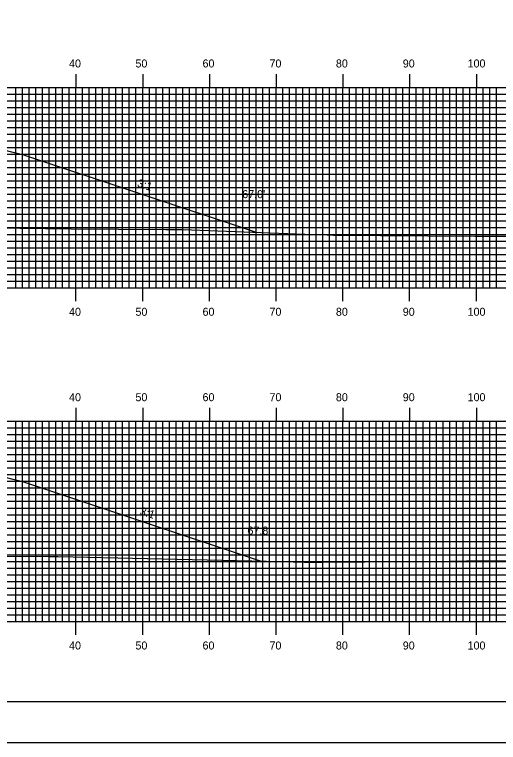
# Model space of a CAD drawing. Extents: x 1806651 to 1806995, y 442591 to 442811.
# Drawn here: x 1806848.1 to 1806920.6, y 442590.5 to 442699.6 of the extents above; entities that cross this region are included whole.
import ezdxf

# ---------------------------------------------------------------- set-up
doc = ezdxf.new("R2010")
doc.units = 0
for name, color, linetype in [('ANNOTATION', 7, 'Continuous'), ('BORDER', 7, 'Continuous'), ('D_Roadway_Centerline', 7, 'Continuous'), ('D_Roadway_SlopeLines', 7, 'Continuous'), ('D_Text_Standard', 7, 'Continuous'), ('H_V ANNOTATION', 7, 'Continuous'), ('MAJOR', 7, 'Continuous'), ('MINOR', 7, 'Continuous'), ('PLOT BOUNDARY', 7, 'Continuous'), ('S_Roadway_Centerline', 7, 'Continuous')]:
    doc.layers.add(name, color=color, linetype=linetype)

msp = doc.modelspace()

# ---------------------------------------------------------------- linework, layer by layer
at = {"layer": 'BORDER'}
msp.add_lwpolyline([(1806667.65, 442596.67), (1806987.65, 442596.67), (1806987.65, 442806.67), (1806667.65, 442806.67)], close=True, dxfattribs=at)
at = {"layer": 'D_Roadway_Centerline'}
for points in [[(1806757.98, 442669.56), (1806785.25, 442678.65), (1806787.07, 442679.1), (1806797.25, 442681.65), (1806805.25, 442681.97), (1806817.25, 442682.21), (1806829.25, 442681.97), (1806837.25, 442681.65), (1806847.42, 442679.1), (1806849.25, 442678.65), (1806884.23, 442666.99)], [(1806759.56, 442621.08), (1806785.25, 442629.65), (1806787.07, 442630.1), (1806797.25, 442632.65), (1806805.25, 442632.97), (1806817.25, 442633.21), (1806829.25, 442632.97), (1806837.25, 442632.65), (1806847.42, 442630.1), (1806849.25, 442629.65), (1806885.01, 442617.73)]]:
    msp.add_lwpolyline(points, dxfattribs=at)
at = {"layer": 'D_Roadway_SlopeLines'}
for points in [[(1806837.25, 442681.65), (1806849.25, 442678.65), (1806884.23, 442666.99)], [(1806837.25, 442632.65), (1806849.25, 442629.65), (1806885.01, 442617.73)]]:
    msp.add_lwpolyline(points, dxfattribs=at)
at = {"layer": 'MAJOR'}
for p, q in [((1806857.25, 442690.67), (1806857.25, 442688.67)), ((1806867.25, 442690.67), (1806867.25, 442688.67)), ((1806877.25, 442690.67), (1806877.25, 442688.67)), ((1806887.25, 442690.67), (1806887.25, 442688.67)), ((1806897.25, 442690.67), (1806897.25, 442688.67)), ((1806907.25, 442690.67), (1806907.25, 442688.67)), ((1806917.25, 442690.67), (1806917.25, 442688.67)), ((1806677.25, 442688.67), (1806957.25, 442688.67)), ((1806677.25, 442688.67), (1806957.25, 442688.67)), ((1806857.25, 442658.67), (1806857.25, 442688.67)), ((1806867.25, 442658.67), (1806867.25, 442688.67)), ((1806877.25, 442658.67), (1806877.25, 442688.67)), ((1806887.25, 442658.67), (1806887.25, 442688.67)), ((1806897.25, 442658.67), (1806897.25, 442688.67)), ((1806907.25, 442658.67), (1806907.25, 442688.67)), ((1806917.25, 442658.67), (1806917.25, 442688.67)), ((1806677.25, 442683.67), (1806957.25, 442683.67)), ((1806677.25, 442678.67), (1806957.25, 442678.67)), ((1806677.25, 442673.67), (1806957.25, 442673.67)), ((1806677.25, 442668.67), (1806957.25, 442668.67)), ((1806677.25, 442663.67), (1806957.25, 442663.67)), ((1806677.25, 442658.67), (1806957.25, 442658.67)), ((1806677.25, 442658.67), (1806957.25, 442658.67)), ((1806857.25, 442656.66), (1806857.25, 442658.67)), ((1806867.25, 442656.66), (1806867.25, 442658.67)), ((1806877.25, 442656.66), (1806877.25, 442658.67)), ((1806887.25, 442656.66), (1806887.25, 442658.67)), ((1806897.25, 442656.66), (1806897.25, 442658.67)), ((1806907.25, 442656.66), (1806907.25, 442658.67)), ((1806917.25, 442656.66), (1806917.25, 442658.67)), ((1806857.25, 442640.67), (1806857.25, 442638.67)), ((1806867.25, 442640.67), (1806867.25, 442638.67)), ((1806877.25, 442640.67), (1806877.25, 442638.67)), ((1806887.25, 442640.67), (1806887.25, 442638.67)), ((1806897.25, 442640.67), (1806897.25, 442638.67)), ((1806907.25, 442640.67), (1806907.25, 442638.67)), ((1806917.25, 442640.67), (1806917.25, 442638.67)), ((1806677.25, 442638.67), (1806957.25, 442638.67)), ((1806677.25, 442638.67), (1806957.25, 442638.67)), ((1806857.25, 442608.67), (1806857.25, 442638.67)), ((1806867.25, 442608.67), (1806867.25, 442638.67)), ((1806877.25, 442608.67), (1806877.25, 442638.67)), ((1806887.25, 442608.67), (1806887.25, 442638.67)), ((1806897.25, 442608.67), (1806897.25, 442638.67)), ((1806907.25, 442608.67), (1806907.25, 442638.67)), ((1806917.25, 442608.67), (1806917.25, 442638.67)), ((1806677.25, 442633.67), (1806957.25, 442633.67)), ((1806677.25, 442628.67), (1806957.25, 442628.67)), ((1806677.25, 442623.67), (1806957.25, 442623.67)), ((1806677.25, 442618.67), (1806957.25, 442618.67)), ((1806677.25, 442613.67), (1806957.25, 442613.67)), ((1806677.25, 442608.67), (1806957.25, 442608.67)), ((1806677.25, 442608.67), (1806957.25, 442608.67)), ((1806857.25, 442606.66), (1806857.25, 442608.67)), ((1806867.25, 442606.66), (1806867.25, 442608.67)), ((1806877.25, 442606.66), (1806877.25, 442608.67)), ((1806887.25, 442606.66), (1806887.25, 442608.67)), ((1806897.25, 442606.66), (1806897.25, 442608.67)), ((1806907.25, 442606.66), (1806907.25, 442608.67)), ((1806917.25, 442606.66), (1806917.25, 442608.67))]:
    msp.add_line(p, q, dxfattribs=at)
at = {"layer": 'MINOR'}
for p, q in [((1806848.25, 442658.67), (1806848.25, 442688.67)), ((1806849.25, 442658.67), (1806849.25, 442688.67)), ((1806850.25, 442658.67), (1806850.25, 442688.67)), ((1806851.25, 442658.67), (1806851.25, 442688.67)), ((1806852.25, 442658.67), (1806852.25, 442688.67)), ((1806853.25, 442658.67), (1806853.25, 442688.67)), ((1806854.25, 442658.67), (1806854.25, 442688.67)), ((1806855.25, 442658.67), (1806855.25, 442688.67)), ((1806856.25, 442658.67), (1806856.25, 442688.67)), ((1806858.25, 442658.67), (1806858.25, 442688.67)), ((1806859.25, 442658.67), (1806859.25, 442688.67)), ((1806860.25, 442658.67), (1806860.25, 442688.67)), ((1806861.25, 442658.67), (1806861.25, 442688.67)), ((1806862.25, 442658.67), (1806862.25, 442688.67)), ((1806863.25, 442658.67), (1806863.25, 442688.67)), ((1806864.25, 442658.67), (1806864.25, 442688.67)), ((1806865.25, 442658.67), (1806865.25, 442688.67)), ((1806866.25, 442658.67), (1806866.25, 442688.67)), ((1806868.25, 442658.67), (1806868.25, 442688.67)), ((1806869.25, 442658.67), (1806869.25, 442688.67)), ((1806870.25, 442658.67), (1806870.25, 442688.67)), ((1806871.25, 442658.67), (1806871.25, 442688.67)), ((1806872.25, 442658.67), (1806872.25, 442688.67)), ((1806873.25, 442658.67), (1806873.25, 442688.67)), ((1806874.25, 442658.67), (1806874.25, 442688.67)), ((1806875.25, 442658.67), (1806875.25, 442688.67)), ((1806876.25, 442658.67), (1806876.25, 442688.67)), ((1806878.25, 442658.67), (1806878.25, 442688.67)), ((1806879.25, 442658.67), (1806879.25, 442688.67)), ((1806880.25, 442658.67), (1806880.25, 442688.67)), ((1806881.25, 442658.67), (1806881.25, 442688.67)), ((1806882.25, 442658.67), (1806882.25, 442688.67)), ((1806883.25, 442658.67), (1806883.25, 442688.67)), ((1806884.25, 442658.67), (1806884.25, 442688.67)), ((1806885.25, 442658.67), (1806885.25, 442688.67)), ((1806886.25, 442658.67), (1806886.25, 442688.67)), ((1806888.25, 442658.67), (1806888.25, 442688.67)), ((1806889.25, 442658.67), (1806889.25, 442688.67)), ((1806890.25, 442658.67), (1806890.25, 442688.67)), ((1806891.25, 442658.67), (1806891.25, 442688.67)), ((1806892.25, 442658.67), (1806892.25, 442688.67)), ((1806893.25, 442658.67), (1806893.25, 442688.67)), ((1806894.25, 442658.67), (1806894.25, 442688.67)), ((1806895.25, 442658.67), (1806895.25, 442688.67)), ((1806896.25, 442658.67), (1806896.25, 442688.67)), ((1806898.25, 442658.67), (1806898.25, 442688.67)), ((1806899.25, 442658.67), (1806899.25, 442688.67)), ((1806900.25, 442658.67), (1806900.25, 442688.67)), ((1806901.25, 442658.67), (1806901.25, 442688.67)), ((1806902.25, 442658.67), (1806902.25, 442688.67)), ((1806903.25, 442658.67), (1806903.25, 442688.67)), ((1806904.25, 442658.67), (1806904.25, 442688.67)), ((1806905.25, 442658.67), (1806905.25, 442688.67)), ((1806906.25, 442658.67), (1806906.25, 442688.67)), ((1806908.25, 442658.67), (1806908.25, 442688.67)), ((1806909.25, 442658.67), (1806909.25, 442688.67)), ((1806910.25, 442658.67), (1806910.25, 442688.67)), ((1806911.25, 442658.67), (1806911.25, 442688.67)), ((1806912.25, 442658.67), (1806912.25, 442688.67)), ((1806913.25, 442658.67), (1806913.25, 442688.67)), ((1806914.25, 442658.67), (1806914.25, 442688.67)), ((1806915.25, 442658.67), (1806915.25, 442688.67)), ((1806916.25, 442658.67), (1806916.25, 442688.67)), ((1806918.25, 442658.67), (1806918.25, 442688.67)), ((1806919.25, 442658.67), (1806919.25, 442688.67)), ((1806920.25, 442658.67), (1806920.25, 442688.67)), ((1806677.25, 442687.67), (1806957.25, 442687.67)), ((1806677.25, 442686.67), (1806957.25, 442686.67)), ((1806677.25, 442685.67), (1806957.25, 442685.67)), ((1806677.25, 442684.67), (1806957.25, 442684.67)), ((1806677.25, 442682.67), (1806957.25, 442682.67)), ((1806677.25, 442681.67), (1806957.25, 442681.67)), ((1806677.25, 442680.67), (1806957.25, 442680.67)), ((1806677.25, 442679.67), (1806957.25, 442679.67)), ((1806677.25, 442677.67), (1806957.25, 442677.67)), ((1806677.25, 442676.67), (1806957.25, 442676.67)), ((1806677.25, 442675.67), (1806957.25, 442675.67)), ((1806677.25, 442674.67), (1806957.25, 442674.67)), ((1806677.25, 442672.67), (1806957.25, 442672.67)), ((1806677.25, 442671.67), (1806957.25, 442671.67)), ((1806677.25, 442670.67), (1806957.25, 442670.67)), ((1806677.25, 442669.67), (1806957.25, 442669.67)), ((1806677.25, 442667.67), (1806957.25, 442667.67)), ((1806677.25, 442666.67), (1806957.25, 442666.67)), ((1806677.25, 442665.67), (1806957.25, 442665.67)), ((1806677.25, 442664.67), (1806957.25, 442664.67)), ((1806677.25, 442662.67), (1806957.25, 442662.67)), ((1806677.25, 442661.67), (1806957.25, 442661.67)), ((1806677.25, 442660.67), (1806957.25, 442660.67)), ((1806677.25, 442659.67), (1806957.25, 442659.67)), ((1806848.25, 442608.67), (1806848.25, 442638.67)), ((1806849.25, 442608.67), (1806849.25, 442638.67)), ((1806850.25, 442608.67), (1806850.25, 442638.67)), ((1806851.25, 442608.67), (1806851.25, 442638.67)), ((1806852.25, 442608.67), (1806852.25, 442638.67)), ((1806853.25, 442608.67), (1806853.25, 442638.67)), ((1806854.25, 442608.67), (1806854.25, 442638.67)), ((1806855.25, 442608.67), (1806855.25, 442638.67)), ((1806856.25, 442608.67), (1806856.25, 442638.67)), ((1806858.25, 442608.67), (1806858.25, 442638.67)), ((1806859.25, 442608.67), (1806859.25, 442638.67)), ((1806860.25, 442608.67), (1806860.25, 442638.67)), ((1806861.25, 442608.67), (1806861.25, 442638.67)), ((1806862.25, 442608.67), (1806862.25, 442638.67)), ((1806863.25, 442608.67), (1806863.25, 442638.67)), ((1806864.25, 442608.67), (1806864.25, 442638.67)), ((1806865.25, 442608.67), (1806865.25, 442638.67)), ((1806866.25, 442608.67), (1806866.25, 442638.67)), ((1806868.25, 442608.67), (1806868.25, 442638.67)), ((1806869.25, 442608.67), (1806869.25, 442638.67)), ((1806870.25, 442608.67), (1806870.25, 442638.67)), ((1806871.25, 442608.67), (1806871.25, 442638.67)), ((1806872.25, 442608.67), (1806872.25, 442638.67)), ((1806873.25, 442608.67), (1806873.25, 442638.67)), ((1806874.25, 442608.67), (1806874.25, 442638.67)), ((1806875.25, 442608.67), (1806875.25, 442638.67)), ((1806876.25, 442608.67), (1806876.25, 442638.67)), ((1806878.25, 442608.67), (1806878.25, 442638.67)), ((1806879.25, 442608.67), (1806879.25, 442638.67)), ((1806880.25, 442608.67), (1806880.25, 442638.67)), ((1806881.25, 442608.67), (1806881.25, 442638.67)), ((1806882.25, 442608.67), (1806882.25, 442638.67)), ((1806883.25, 442608.67), (1806883.25, 442638.67)), ((1806884.25, 442608.67), (1806884.25, 442638.67)), ((1806885.25, 442608.67), (1806885.25, 442638.67)), ((1806886.25, 442608.67), (1806886.25, 442638.67)), ((1806888.25, 442608.67), (1806888.25, 442638.67)), ((1806889.25, 442608.67), (1806889.25, 442638.67)), ((1806890.25, 442608.67), (1806890.25, 442638.67)), ((1806891.25, 442608.67), (1806891.25, 442638.67)), ((1806892.25, 442608.67), (1806892.25, 442638.67)), ((1806893.25, 442608.67), (1806893.25, 442638.67)), ((1806894.25, 442608.67), (1806894.25, 442638.67)), ((1806895.25, 442608.67), (1806895.25, 442638.67)), ((1806896.25, 442608.67), (1806896.25, 442638.67)), ((1806898.25, 442608.67), (1806898.25, 442638.67)), ((1806899.25, 442608.67), (1806899.25, 442638.67)), ((1806900.25, 442608.67), (1806900.25, 442638.67)), ((1806901.25, 442608.67), (1806901.25, 442638.67)), ((1806902.25, 442608.67), (1806902.25, 442638.67)), ((1806903.25, 442608.67), (1806903.25, 442638.67)), ((1806904.25, 442608.67), (1806904.25, 442638.67)), ((1806905.25, 442608.67), (1806905.25, 442638.67)), ((1806906.25, 442608.67), (1806906.25, 442638.67)), ((1806908.25, 442608.67), (1806908.25, 442638.67)), ((1806909.25, 442608.67), (1806909.25, 442638.67)), ((1806910.25, 442608.67), (1806910.25, 442638.67)), ((1806911.25, 442608.67), (1806911.25, 442638.67)), ((1806912.25, 442608.67), (1806912.25, 442638.67)), ((1806913.25, 442608.67), (1806913.25, 442638.67)), ((1806914.25, 442608.67), (1806914.25, 442638.67)), ((1806915.25, 442608.67), (1806915.25, 442638.67)), ((1806916.25, 442608.67), (1806916.25, 442638.67)), ((1806918.25, 442608.67), (1806918.25, 442638.67)), ((1806919.25, 442608.67), (1806919.25, 442638.67)), ((1806920.25, 442608.67), (1806920.25, 442638.67)), ((1806677.25, 442637.67), (1806957.25, 442637.67)), ((1806677.25, 442636.67), (1806957.25, 442636.67)), ((1806677.25, 442635.67), (1806957.25, 442635.67)), ((1806677.25, 442634.67), (1806957.25, 442634.67)), ((1806677.25, 442632.67), (1806957.25, 442632.67)), ((1806677.25, 442631.67), (1806957.25, 442631.67)), ((1806677.25, 442630.67), (1806957.25, 442630.67)), ((1806677.25, 442629.67), (1806957.25, 442629.67)), ((1806677.25, 442627.67), (1806957.25, 442627.67)), ((1806677.25, 442626.67), (1806957.25, 442626.67)), ((1806677.25, 442625.67), (1806957.25, 442625.67)), ((1806677.25, 442624.67), (1806957.25, 442624.67)), ((1806677.25, 442622.67), (1806957.25, 442622.67)), ((1806677.25, 442621.67), (1806957.25, 442621.67)), ((1806677.25, 442620.67), (1806957.25, 442620.67)), ((1806677.25, 442619.67), (1806957.25, 442619.67)), ((1806677.25, 442617.67), (1806957.25, 442617.67)), ((1806677.25, 442616.67), (1806957.25, 442616.67)), ((1806677.25, 442615.67), (1806957.25, 442615.67)), ((1806677.25, 442614.67), (1806957.25, 442614.67)), ((1806677.25, 442612.67), (1806957.25, 442612.67)), ((1806677.25, 442611.67), (1806957.25, 442611.67)), ((1806677.25, 442610.67), (1806957.25, 442610.67)), ((1806677.25, 442609.67), (1806957.25, 442609.67))]:
    msp.add_line(p, q, dxfattribs=at)
at = {"layer": 'PLOT BOUNDARY'}
msp.add_lwpolyline([(1806651.46, 442590.55), (1806991.46, 442590.55), (1806991.46, 442810.55), (1806651.46, 442810.55)], close=True, dxfattribs=at)
at = {"layer": 'S_Roadway_Centerline'}
for points in [[(1806821.89, 442667.95), (1806856.56, 442667.51), (1806870.7, 442667.4), (1806873.25, 442667.39), (1806891.61, 442666.72), (1806894.85, 442666.6), (1806895.82, 442666.57), (1806917, 442666.38), (1806919.2, 442666.38), (1806921.92, 442666.4), (1806944.01, 442666.14), (1806950.5, 442665.91), (1806955.14, 442665.87), (1806957.25, 442665.89)], [(1806835.26, 442618.46), (1806853.24, 442618.41), (1806854.41, 442618.41), (1806854.59, 442618.41), (1806888.04, 442617.66), (1806891.49, 442617.57), (1806894.18, 442617.58), (1806913.19, 442617.71), (1806915.76, 442617.74), (1806926.18, 442617.8), (1806930.78, 442617.41), (1806957.25, 442617.28)]]:
    msp.add_lwpolyline(points, dxfattribs=at)

# ---------------------------------------------------------------- texts
at = {"layer": 'ANNOTATION'}
for p in [(1806866.34, 442673.86), (1806866.73, 442624.73)]:
    msp.add_text('3:1', height=1.2, rotation=341.5652, dxfattribs=at).set_placement(p)
at = {"layer": 'D_Text_Standard'}
for s, p in [("67.0'", (1806882.17, 442672.09)), ("67.8'", (1806882.95, 442621.69))]:
    msp.add_text(s, height=1.2, dxfattribs=at).set_placement(p)
at = {"layer": 'H_V ANNOTATION'}
for s, p in [('40', (1806856.22, 442691.67)), ('50', (1806866.17, 442691.67)), ('60', (1806876.22, 442691.67)), ('70', (1806886.25, 442691.67)), ('80', (1806896.2, 442691.67)), ('90', (1806906.22, 442691.67)), ('100', (1806915.93, 442691.67)), ('40', (1806856.22, 442654.47)), ('50', (1806866.17, 442654.47)), ('60', (1806876.22, 442654.47)), ('70', (1806886.25, 442654.47)), ('80', (1806896.2, 442654.47)), ('90', (1806906.22, 442654.47)), ('100', (1806915.93, 442654.47)), ('40', (1806856.22, 442641.67)), ('50', (1806866.17, 442641.67)), ('60', (1806876.22, 442641.67)), ('70', (1806886.25, 442641.67)), ('80', (1806896.2, 442641.67)), ('90', (1806906.22, 442641.67)), ('100', (1806915.93, 442641.67)), ('40', (1806856.22, 442604.47)), ('50', (1806866.17, 442604.47)), ('60', (1806876.22, 442604.47)), ('70', (1806886.25, 442604.47)), ('80', (1806896.2, 442604.47)), ('90', (1806906.22, 442604.47)), ('100', (1806915.93, 442604.47))]:
    msp.add_text(s, height=1.2, dxfattribs=at).set_placement(p)

doc.saveas('drawing.dxf')
